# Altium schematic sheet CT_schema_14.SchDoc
size 387 x 278 mm
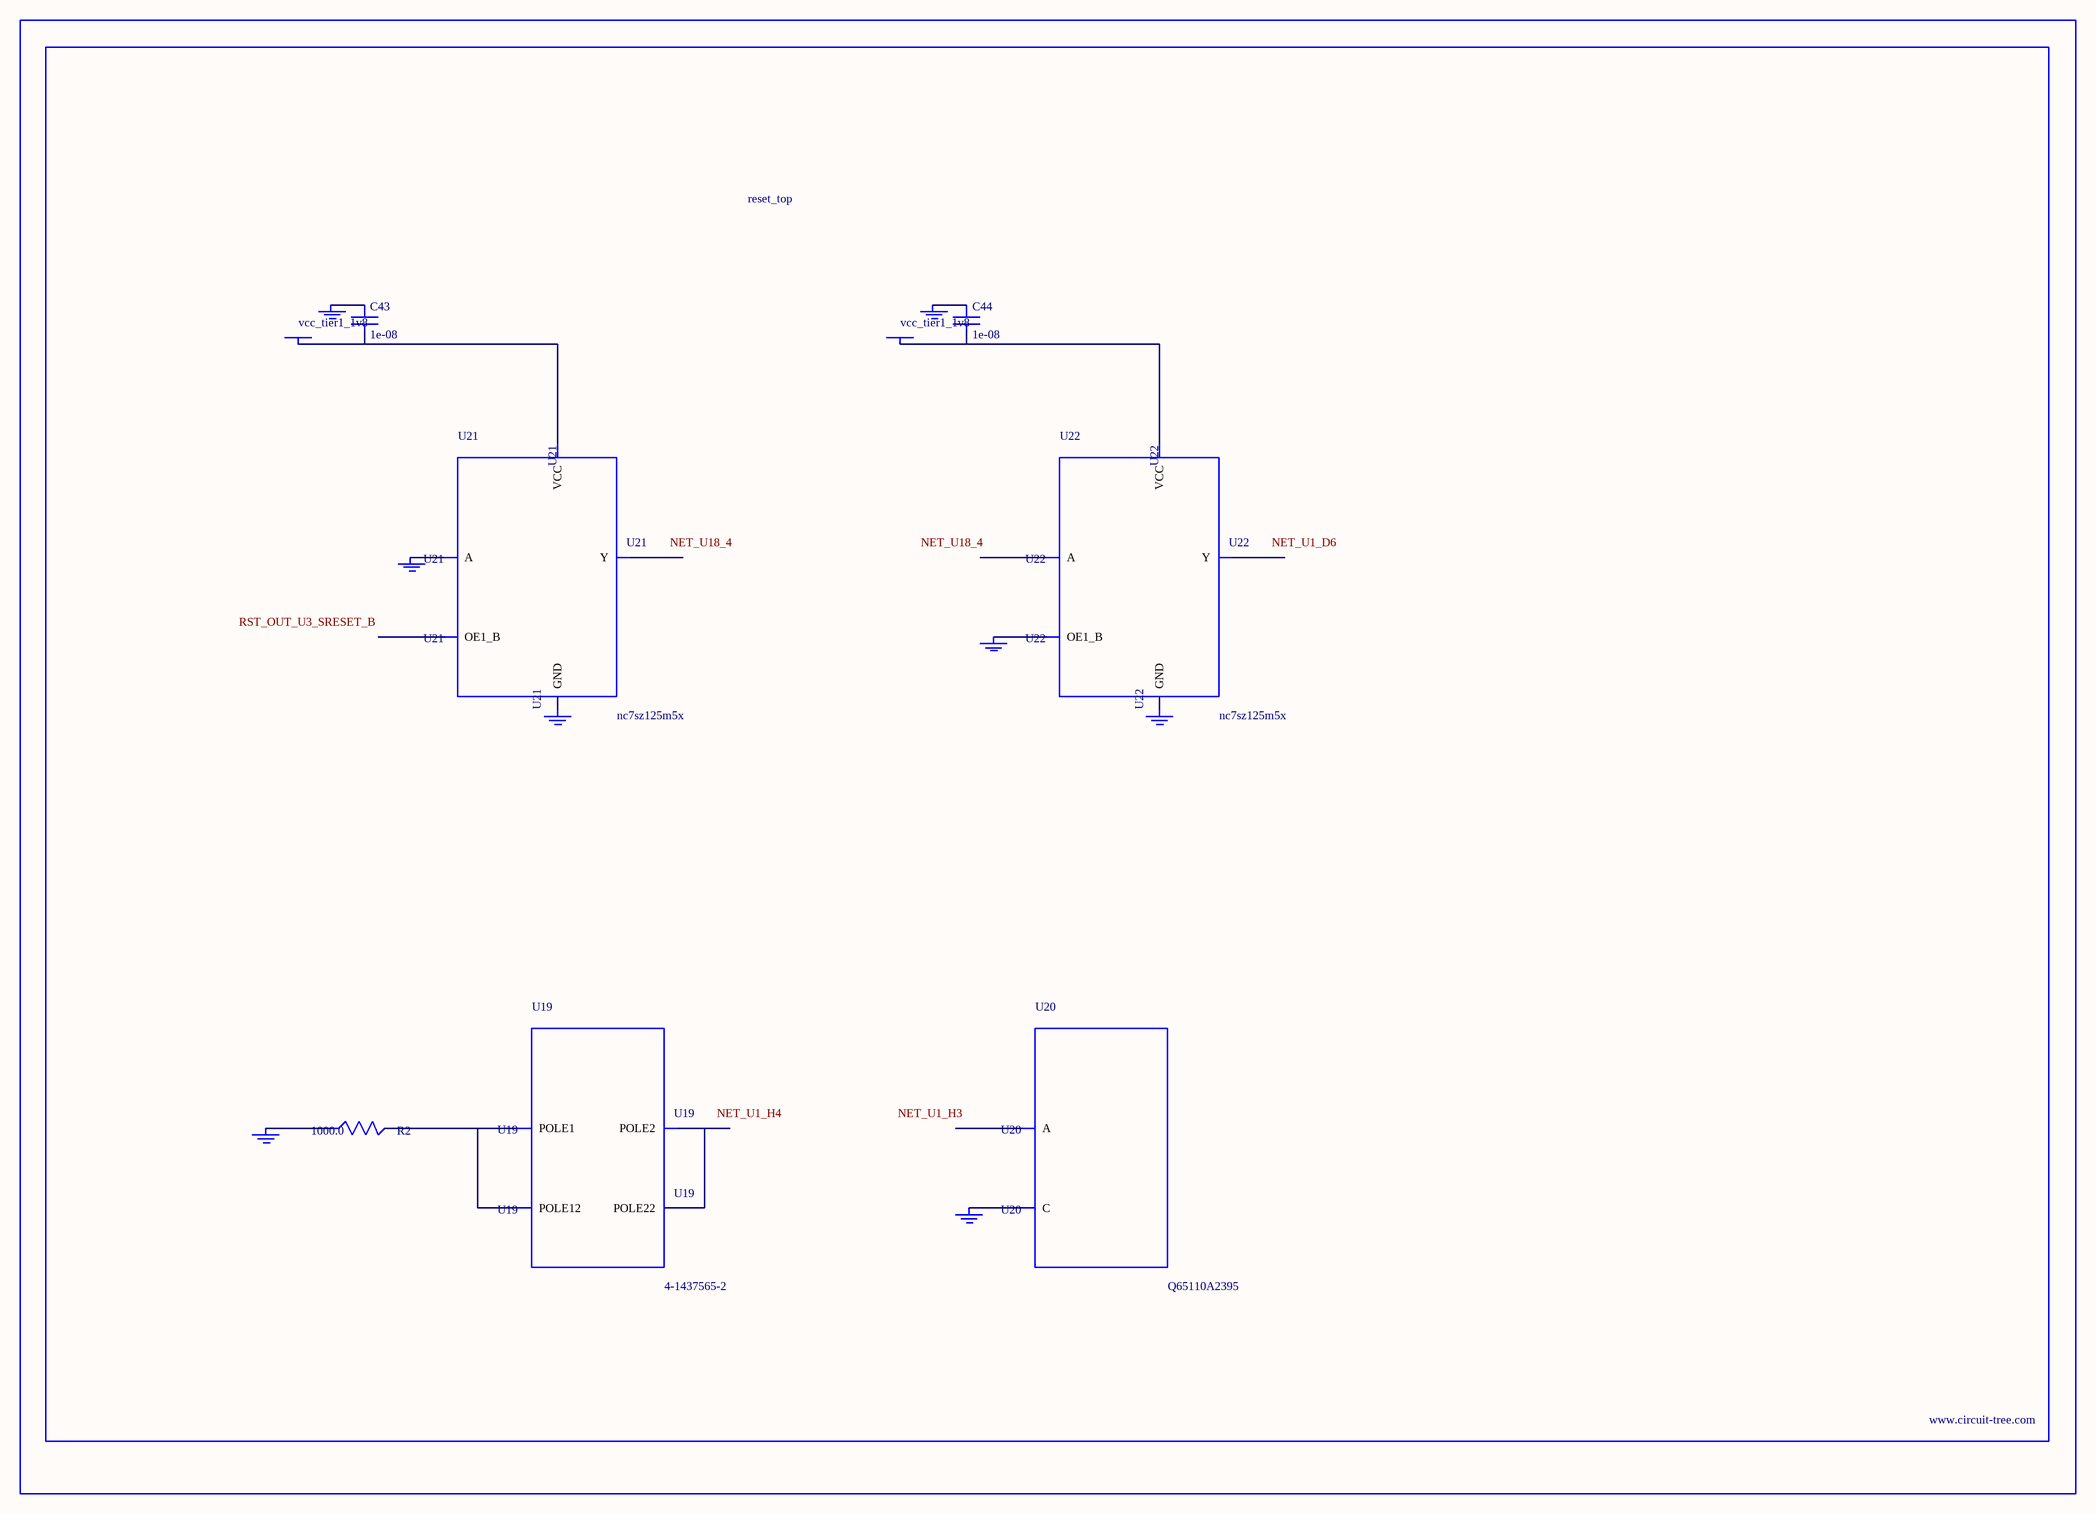
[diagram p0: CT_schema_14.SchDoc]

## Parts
BORDER13  (no value)
C43  1e-08  [C0402]
C44  1e-08  [C0402]
GND_INSTANCE_13_0  (no value)
GND_INSTANCE_13_1  (no value)
GND_INSTANCE_13_2  (no value)
GND_INSTANCE_13_3  (no value)
GND_INSTANCE_13_4  (no value)
GND_INSTANCE_13_5  (no value)
GND_INSTANCE_13_6  (no value)
GND_INSTANCE_13_7  (no value)
POWER_INSTANCE_13_0  vcc_tier1_1v8
POWER_INSTANCE_13_1  vcc_tier1_1v8
R2  1000.0  [R0603]
U19  4-1437565-2  [SW_4-1437565-2]
U20  Q65110A2395  [LGM67K-G1J2-24-Z]
U21  nc7sz125m5x  [NC7SZ125M5X]
U22  nc7sz125m5x  [NC7SZ125M5X]

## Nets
NetC43_1: C43.1 GND_INSTANCE_13_2.0(GND)
NetC43_2: C43.2 POWER_INSTANCE_13_0.0(PWR) U21.5(VCC)
NetC44_1: C44.1 GND_INSTANCE_13_5.0(GND)
NetC44_2: C44.2 POWER_INSTANCE_13_1.0(PWR) U22.5(VCC)
NetGND_INSTANCE_13_0_0: GND_INSTANCE_13_0.0(GND) R2.1
NetGND_INSTANCE_13_1_0: GND_INSTANCE_13_1.0(GND) U20.C
NetGND_INSTANCE_13_3_0: GND_INSTANCE_13_3.0(GND) U21.2(A)
NetGND_INSTANCE_13_4_0: GND_INSTANCE_13_4.0(GND) U21.3(GND)
NetGND_INSTANCE_13_6_0: GND_INSTANCE_13_6.0(GND) U22.1(OE1_B)
NetGND_INSTANCE_13_7_0: GND_INSTANCE_13_7.0(GND) U22.3(GND)
NetR2_2: R2.2 U19.1(POLE1) U19.2(POLE12)
NetU19_3: U19.3(POLE2) U19.4(POLE22)

Not connected (* = marked no-connect by the designer): U20 A; U21 1(OE1_B) 4(Y); U22 2(A) 4(Y)

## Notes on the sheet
- Labels drawn without touching a wire or pin: NET_U1_D6, NET_U1_H3, NET_U1_H4, NET_U18_4, RST_OUT_U3_SRESET_B

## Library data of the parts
BORDER13 = BORDER_PAGE13
C43 C44 = C0402C103K3RAC
GND_INSTANCE_13_0-GND_INSTANCE_13_7 = GND
POWER_INSTANCE_13_0 POWER_INSTANCE_13_1 = PWR
R2 = RC0603JR-071KL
